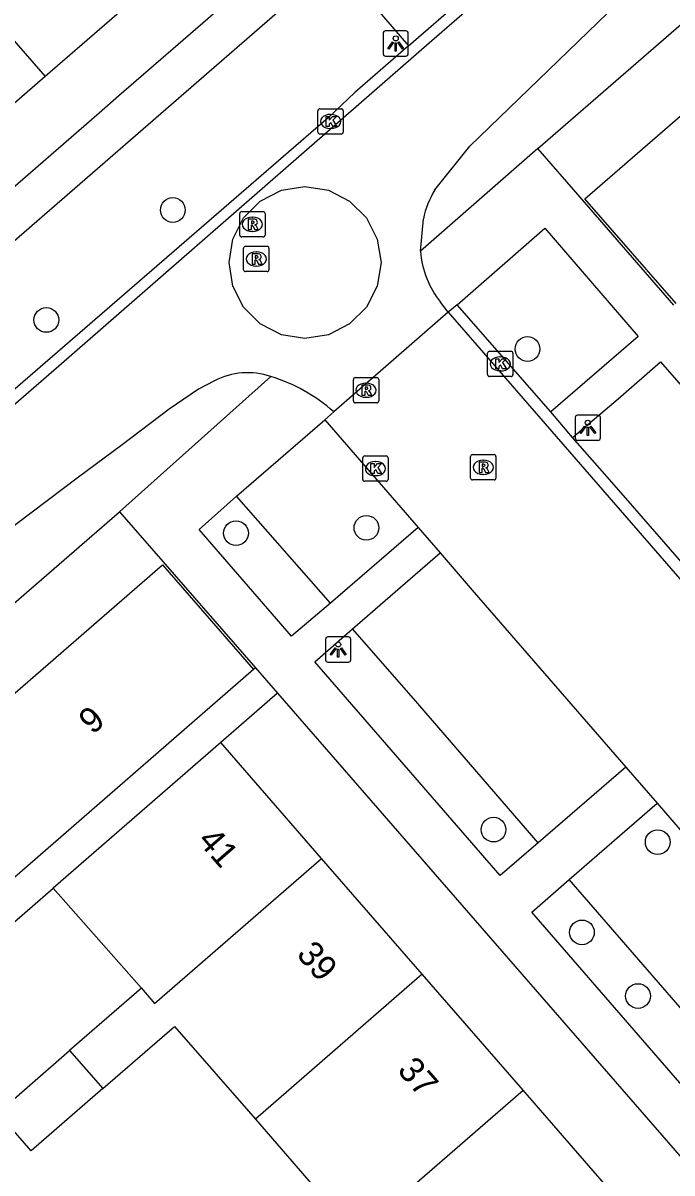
# Model space of a CAD drawing. Extents: x 155888 to 156864, y 383882 to 384671.
# Drawn here: x 156567.31 to 156592.97, y 384066.28 to 384111.77 of the extents above; entities that cross this region are included whole.
import ezdxf

# ---------------------------------------------------------------- set-up
doc = ezdxf.new("R2010")
doc.units = 0
for name, color, linetype in [('IMGEO_Boom', 7, 'Continuous'), ('IMGEO_Kolk', 7, 'Continuous'), ('IMGEO_Lichtpunt', 7, 'Continuous'), ('IMGEO_Pand', 7, 'Continuous'), ('IMGEO_Pand_nummerreeks', 7, 'Continuous'), ('IMGEO_Parkeervlak_open', 7, 'Continuous'), ('IMGEO_Rijbaan_lokaal_gesloten', 7, 'Continuous'), ('IMGEO_Rijbaan_lokaal_open', 7, 'Continuous'), ('IMGEO_Rioolput', 7, 'Continuous'), ('IMGEO_Voetpad_open', 7, 'Continuous')]:
    doc.layers.add(name, color=color, linetype=linetype)

msp = doc.modelspace()

# ---------------------------------------------------------------- linework, layer by layer
at = {"layer": 'IMGEO_Boom'}
for centre in [(156573.237, 384104.376), (156568.236, 384100.027), (156587.258, 384098.878), (156575.735, 384091.594), (156580.891, 384091.805), (156585.915, 384079.868), (156592.406, 384079.372), (156589.41, 384075.802), (156591.628, 384073.284)]:
    msp.add_circle(centre, 0.489, dxfattribs=at)
at = {"layer": 'IMGEO_Kolk'}
for p, q in [((156578.972, 384107.452), (156578.972, 384108.304)), ((156579.047, 384108.378), (156579.899, 384108.378)), ((156579.973, 384108.304), (156579.973, 384107.452)), ((156579.46, 384108.158), (156579.485, 384108.158)), ((156579.899, 384107.378), (156579.047, 384107.378)), ((156579.483, 384107.598), (156579.458, 384107.598)), ((156585.682, 384097.865), (156585.682, 384098.717)), ((156585.757, 384098.791), (156586.609, 384098.791)), ((156586.683, 384098.717), (156586.683, 384097.865)), ((156586.17, 384098.571), (156586.195, 384098.571)), ((156586.193, 384098.011), (156586.168, 384098.011)), ((156586.609, 384097.791), (156585.757, 384097.791)), ((156580.823, 384094.648), (156581.675, 384094.648)), ((156580.748, 384093.722), (156580.748, 384094.574)), ((156581.236, 384094.428), (156581.261, 384094.428)), ((156581.749, 384094.574), (156581.749, 384093.722)), ((156581.259, 384093.868), (156581.234, 384093.868)), ((156581.675, 384093.648), (156580.823, 384093.648))]:
    msp.add_line(p, q, dxfattribs=at)
for points in [[(156578.972, 384107.452), (156578.972, 384108.304)], [(156579.047, 384108.378), (156579.899, 384108.378)], [(156579.973, 384108.304), (156579.973, 384107.452)], [(156579.293, 384108.078), (156579.416, 384108.078), (156579.416, 384107.927), (156579.546, 384108.078), (156579.71, 384108.078), (156579.564, 384107.927), (156579.717, 384107.678), (156579.565, 384107.678), (156579.48, 384107.842), (156579.416, 384107.775), (156579.416, 384107.678), (156579.293, 384107.678), (156579.293, 384108.078)], [(156579.899, 384107.378), (156579.047, 384107.378)], [(156585.682, 384097.865), (156585.682, 384098.717)], [(156585.757, 384098.791), (156586.609, 384098.791)], [(156586.683, 384098.717), (156586.683, 384097.865)], [(156586.003, 384098.491), (156586.126, 384098.491), (156586.126, 384098.34), (156586.256, 384098.491), (156586.42, 384098.491), (156586.274, 384098.34), (156586.427, 384098.091), (156586.275, 384098.091), (156586.19, 384098.255), (156586.126, 384098.188), (156586.126, 384098.091), (156586.003, 384098.091), (156586.003, 384098.491)], [(156586.609, 384097.791), (156585.757, 384097.791)], [(156580.823, 384094.648), (156581.675, 384094.648)], [(156580.748, 384093.722), (156580.748, 384094.574)], [(156581.069, 384094.348), (156581.192, 384094.348), (156581.192, 384094.197), (156581.322, 384094.348), (156581.486, 384094.348), (156581.34, 384094.197), (156581.493, 384093.948), (156581.341, 384093.948), (156581.256, 384094.112), (156581.192, 384094.045), (156581.192, 384093.948), (156581.069, 384093.948), (156581.069, 384094.348)], [(156581.749, 384094.574), (156581.749, 384093.722)], [(156581.675, 384093.648), (156580.823, 384093.648)]]:
    msp.add_lwpolyline(points, dxfattribs=at)
for centre, start, end in [((156579.049, 384108.302), 91.552, 178.448), ((156579.049, 384108.302), 91.552, 178.448), ((156579.897, 384108.302), 1.552, 88.448), ((156579.897, 384108.302), 1.552, 88.448), ((156579.049, 384107.454), 181.552, 268.448), ((156579.049, 384107.454), 181.552, 268.448), ((156579.897, 384107.454), 271.552, 358.448), ((156579.897, 384107.454), 271.552, 358.448), ((156585.759, 384098.715), 91.552, 178.448), ((156585.759, 384098.715), 91.552, 178.448), ((156586.607, 384098.715), 1.552, 88.448), ((156586.607, 384098.715), 1.552, 88.448), ((156585.759, 384097.867), 181.552, 268.448), ((156585.759, 384097.867), 181.552, 268.448), ((156586.607, 384097.867), 271.552, 358.448), ((156586.607, 384097.867), 271.552, 358.448), ((156580.825, 384094.572), 91.552, 178.448), ((156580.825, 384094.572), 91.552, 178.448), ((156581.673, 384094.572), 1.552, 88.448), ((156581.673, 384094.572), 1.552, 88.448), ((156580.825, 384093.724), 181.552, 268.448), ((156580.825, 384093.724), 181.552, 268.448), ((156581.673, 384093.724), 271.552, 358.448), ((156581.673, 384093.724), 271.552, 358.448)]:
    msp.add_arc(centre, 0.0765, start, end, dxfattribs=at)
for centre, major_axis, ratio, start_param, end_param in [((156579.459, 384107.878), (-0.387, 0.002), 0.722429, 4.712389, 7.853982), ((156579.484, 384107.878), (-0.39, 0.002), 0.717154, 1.570796, 4.712389), ((156586.169, 384098.291), (-0.387, 0.002), 0.722429, 4.712389, 7.853982), ((156586.194, 384098.291), (-0.39, 0.002), 0.717154, 1.570796, 4.712389), ((156581.235, 384094.148), (-0.387, 0.002), 0.722429, 4.712389, 7.853982), ((156581.26, 384094.148), (-0.39, 0.002), 0.717154, 1.570796, 4.712389)]:
    msp.add_ellipse(centre, major_axis=major_axis, ratio=ratio, start_param=start_param, end_param=end_param, dxfattribs=at)
at = {"layer": 'IMGEO_Lichtpunt'}
for p, q in [((156582.451, 384111.462), (156581.643, 384111.462)), ((156582.451, 384111.462), (156581.643, 384111.462)), ((156581.549, 384111.367), (156581.549, 384110.56)), ((156581.549, 384111.367), (156581.549, 384110.56)), ((156582.545, 384110.56), (156582.545, 384111.367)), ((156582.545, 384110.56), (156582.545, 384111.367)), ((156581.643, 384110.466), (156582.451, 384110.466)), ((156581.643, 384110.466), (156582.451, 384110.466)), ((156589.143, 384096.167), (156589.143, 384095.36)), ((156589.143, 384096.167), (156589.143, 384095.36)), ((156590.045, 384096.262), (156589.237, 384096.262)), ((156590.045, 384096.262), (156589.237, 384096.262)), ((156590.139, 384095.36), (156590.139, 384096.167)), ((156590.139, 384095.36), (156590.139, 384096.167)), ((156589.237, 384095.266), (156590.045, 384095.266)), ((156589.237, 384095.266), (156590.045, 384095.266)), ((156579.275, 384087.394), (156579.275, 384086.587)), ((156579.275, 384087.394), (156579.275, 384086.587)), ((156580.177, 384087.489), (156579.369, 384087.489)), ((156580.177, 384087.489), (156579.369, 384087.489)), ((156580.271, 384086.587), (156580.271, 384087.394)), ((156580.271, 384086.587), (156580.271, 384087.394)), ((156579.369, 384086.493), (156580.177, 384086.493)), ((156579.369, 384086.493), (156580.177, 384086.493))]:
    msp.add_line(p, q, dxfattribs=at)
for points in [[(156581.923, 384111.031), (156581.962, 384111.003), (156581.774, 384110.741), (156581.736, 384110.768), (156581.923, 384111.031)], [(156582.135, 384111.003), (156582.173, 384111.03), (156582.36, 384110.768), (156582.321, 384110.74), (156582.135, 384111.003)], [(156582.025, 384110.983), (156582.072, 384110.983), (156582.072, 384110.661), (156582.025, 384110.661), (156582.025, 384110.983)], [(156589.517, 384095.831), (156589.556, 384095.803), (156589.368, 384095.541), (156589.33, 384095.568), (156589.517, 384095.831)], [(156589.619, 384095.783), (156589.666, 384095.783), (156589.666, 384095.461), (156589.619, 384095.461), (156589.619, 384095.783)], [(156589.729, 384095.803), (156589.767, 384095.83), (156589.954, 384095.568), (156589.915, 384095.54), (156589.729, 384095.803)], [(156579.649, 384087.058), (156579.688, 384087.03), (156579.5, 384086.768), (156579.462, 384086.795), (156579.649, 384087.058)], [(156579.751, 384087.01), (156579.798, 384087.01), (156579.798, 384086.688), (156579.751, 384086.688), (156579.751, 384087.01)], [(156579.861, 384087.03), (156579.899, 384087.057), (156580.086, 384086.795), (156580.047, 384086.767), (156579.861, 384087.03)]]:
    msp.add_lwpolyline(points, dxfattribs=at)
for centre in [(156582.048, 384111.165), (156589.642, 384095.965), (156579.774, 384087.192)]:
    msp.add_circle(centre, 0.0994, dxfattribs=at)
for centre, start, end in [((156581.643, 384111.367), 90, 180), ((156581.643, 384111.367), 90, 180), ((156582.451, 384111.367), 0, 90), ((156582.451, 384111.367), 0, 90), ((156581.643, 384110.56), 180, 270), ((156581.643, 384110.56), 180, 270), ((156582.451, 384110.56), 270, 0), ((156582.451, 384110.56), 270, 360), ((156589.237, 384096.167), 90, 180), ((156589.237, 384096.167), 90, 180), ((156590.045, 384096.167), 0, 90), ((156590.045, 384096.167), 0, 90), ((156589.237, 384095.36), 180, 270), ((156589.237, 384095.36), 180, 270), ((156590.045, 384095.36), 270, 0), ((156590.045, 384095.36), 270, 360), ((156579.369, 384087.394), 90, 180), ((156579.369, 384087.394), 90, 180), ((156580.177, 384087.394), 0, 90), ((156580.177, 384087.394), 0, 90), ((156579.369, 384086.587), 180, 270), ((156579.369, 384086.587), 180, 270), ((156580.177, 384086.587), 270, 0), ((156580.177, 384086.587), 270, 360)]:
    msp.add_arc(centre, 0.0946, start, end, dxfattribs=at)
at = {"layer": 'IMGEO_Pand'}
for points in [[(156560.961, 384117.973), (156568.188, 384109.654)], [(156572.48, 384113.384), (156568.188, 384109.654)], [(156593.133, 384100.673), (156589.53, 384104.822), (156599.132, 384113.164)], [(156568.188, 384109.654), (156563.88, 384105.911)], [(156563.279, 384082.047), (156572.833, 384090.346), (156576.432, 384086.204)], [(156576.432, 384086.204), (156566.883, 384077.899)], [(156575.131, 384083.315), (156568.505, 384077.555)], [(156579.116, 384078.729), (156575.131, 384083.315)], [(156571.995, 384073.595), (156572.516, 384072.995), (156579.116, 384078.729)], [(156583.1, 384074.145), (156579.116, 384078.729)], [(156568.505, 384077.555), (156571.995, 384073.595)], [(156583.1, 384074.145), (156576.499, 384068.41)], [(156587.084, 384069.561), (156583.1, 384074.145)], [(156571.995, 384073.595), (156569.158, 384071.13)], [(156570.469, 384069.621), (156573.306, 384072.086), (156576.499, 384068.41)], [(156570.469, 384069.621), (156567.631, 384067.156), (156566.842, 384068.065), (156566.32, 384068.665), (156569.158, 384071.13)], [(156569.158, 384071.13), (156570.469, 384069.621)], [(156579.882, 384064.517), (156580.483, 384063.825), (156587.084, 384069.561)], [(156591.067, 384064.978), (156587.084, 384069.561)], [(156576.499, 384068.41), (156579.882, 384064.517)]]:
    msp.add_lwpolyline(points, dxfattribs=at)
at = {"layer": 'IMGEO_Parkeervlak_open'}
for points in [[(156579.467, 384088.82), (156575.754, 384093.051)], [(156587.675, 384079.35), (156582.75, 384085.048), (156580.345, 384087.815)], [(156595.54, 384070.25), (156588.905, 384077.888)]]:
    msp.add_lwpolyline(points, dxfattribs=at)
at = {"layer": 'IMGEO_Rijbaan_lokaal_gesloten'}
for points in [[(156528.389, 384063.906), (156532.781, 384067.236), (156536.903, 384070.55), (156552.177, 384083.855), (156568.729, 384098.213), (156583.48, 384111.077), (156616.441, 384139.692), (156618.873, 384141.904), (156620.066, 384143.035), (156621.243, 384144.182), (156623.55, 384146.525), (156624.152, 384147.224), (156624.451, 384147.625)], [(156583.599, 384105.173), (156584.982, 384106.904), (156592.374, 384114.06), (156593.839, 384115.427), (156617.343, 384135.911), (156620.351, 384138.467), (156622.416, 384140.04), (156625.179, 384141.829)], [(156583.03, 384102.742), (156583.141, 384104.026)], [(156584.127, 384100.331), (156583.822, 384100.726)], [(156584.127, 384100.331), (156579.597, 384096.394)], [(156584.127, 384100.331), (156646.454, 384028.54), (156658.614, 384014.564)], [(156574.884, 384097.615), (156574.254, 384097.287), (156573.089, 384096.493), (156571.232, 384095.093), (156569.511, 384093.811), (156565.774, 384090.997), (156564.52, 384089.962), (156545.807, 384073.68), (156537.825, 384066.685), (156535.938, 384064.836), (156531.519, 384060.256)], [(156579.597, 384096.394), (156579.244, 384096.079)], [(156579.244, 384096.079), (156582.931, 384091.822)], [(156582.931, 384091.822), (156583.811, 384090.821)], [(156583.811, 384090.821), (156585.156, 384089.249), (156586.193, 384088.05), (156591.142, 384082.341)], [(156591.142, 384082.341), (156592.38, 384080.913)], [(156592.38, 384080.913), (156599, 384073.239)]]:
    msp.add_lwpolyline(points, dxfattribs=at)
for centre, radius, start, end in [((156586.512, 384103.345), 3.439, 147.8892, 168.5769), ((156586.652, 384103.001), 3.631, 184.0939, 218.8015), ((156576.196, 384095.132), 2.808, 70.979, 117.8538), ((156575.17, 384091.407), 6.669, 48.3992, 73.0737)]:
    msp.add_arc(centre, radius, start, end, dxfattribs=at)
at = {"layer": 'IMGEO_Rijbaan_lokaal_open'}
for points in [[(156582.557, 384110.877), (156584.84, 384112.864)], [(156582.557, 384110.877), (156580.429, 384109.026), (156579.376, 384108.016), (156553.553, 384085.656), (156552.051, 384084.344)], [(156581.319, 384101.37), (156580.893, 384100.533), (156580.228, 384099.868), (156579.391, 384099.442), (156578.462, 384099.295), (156577.534, 384099.442), (156576.696, 384099.868), (156576.032, 384100.533), (156575.605, 384101.37), (156575.458, 384102.299), (156575.605, 384103.227), (156576.032, 384104.065), (156576.696, 384104.729), (156577.534, 384105.156), (156578.462, 384105.303), (156579.391, 384105.156), (156580.228, 384104.729), (156580.893, 384104.065), (156581.319, 384103.227), (156581.467, 384102.299), (156581.319, 384101.37)], [(156584.474, 384100.632), (156584.127, 384100.331)], [(156588.18, 384096.392), (156584.474, 384100.632)], [(156589.043, 384095.382), (156588.18, 384096.392)], [(156596.453, 384086.892), (156594.77, 384088.811), (156591.404, 384092.681), (156590.413, 384093.818), (156589.043, 384095.382)]]:
    msp.add_lwpolyline(points, dxfattribs=at)
at = {"layer": 'IMGEO_Rioolput'}
for p, q in [((156575.884, 384103.385), (156575.884, 384104.237)), ((156575.959, 384104.311), (156576.811, 384104.311)), ((156576.885, 384104.237), (156576.885, 384103.385)), ((156576.372, 384104.091), (156576.397, 384104.091)), ((156576.811, 384103.311), (156575.959, 384103.311)), ((156576.395, 384103.531), (156576.37, 384103.531)), ((156576.037, 384102.014), (156576.037, 384102.866)), ((156576.112, 384102.94), (156576.964, 384102.94)), ((156577.038, 384102.866), (156577.038, 384102.014)), ((156576.525, 384102.72), (156576.55, 384102.72)), ((156576.964, 384101.94), (156576.112, 384101.94)), ((156576.548, 384102.16), (156576.523, 384102.16)), ((156580.376, 384096.823), (156580.376, 384097.675)), ((156580.451, 384097.749), (156581.303, 384097.749)), ((156580.864, 384097.529), (156580.889, 384097.529)), ((156581.377, 384097.675), (156581.377, 384096.823)), ((156580.887, 384096.969), (156580.862, 384096.969)), ((156581.303, 384096.749), (156580.451, 384096.749)), ((156585.009, 384093.773), (156585.009, 384094.625)), ((156585.084, 384094.699), (156585.936, 384094.699)), ((156586.01, 384094.625), (156586.01, 384093.773)), ((156585.497, 384094.479), (156585.522, 384094.479)), ((156585.52, 384093.919), (156585.495, 384093.919)), ((156585.936, 384093.699), (156585.084, 384093.699))]:
    msp.add_line(p, q, dxfattribs=at)
for points in [[(156575.884, 384103.385), (156575.884, 384104.237)], [(156575.959, 384104.311), (156576.811, 384104.311)], [(156576.885, 384104.237), (156576.885, 384103.385)], [(156576.473, 384104.009), (156576.221, 384104.011), (156576.221, 384103.611)], [(156576.221, 384103.611), (156576.345, 384103.611), (156576.345, 384103.773), (156576.356, 384103.773)], [(156576.399, 384103.93), (156576.345, 384103.93), (156576.345, 384103.849)], [(156576.345, 384103.849), (156576.397, 384103.849)], [(156576.403, 384103.744), (156576.474, 384103.611), (156576.614, 384103.611), (156576.549, 384103.737)], [(156576.811, 384103.311), (156575.959, 384103.311)], [(156576.037, 384102.014), (156576.037, 384102.866)], [(156576.112, 384102.94), (156576.964, 384102.94)], [(156577.038, 384102.866), (156577.038, 384102.014)], [(156576.626, 384102.638), (156576.374, 384102.64), (156576.374, 384102.24)], [(156576.374, 384102.24), (156576.498, 384102.24), (156576.498, 384102.402), (156576.509, 384102.402)], [(156576.552, 384102.559), (156576.498, 384102.559), (156576.498, 384102.478)], [(156576.498, 384102.478), (156576.55, 384102.478)], [(156576.556, 384102.373), (156576.627, 384102.24), (156576.767, 384102.24), (156576.702, 384102.366)], [(156576.964, 384101.94), (156576.112, 384101.94)], [(156580.376, 384096.823), (156580.376, 384097.675)], [(156580.451, 384097.749), (156581.303, 384097.749)], [(156580.965, 384097.447), (156580.713, 384097.449), (156580.713, 384097.049)], [(156580.891, 384097.368), (156580.837, 384097.368), (156580.837, 384097.287)], [(156581.377, 384097.675), (156581.377, 384096.823)], [(156580.713, 384097.049), (156580.837, 384097.049), (156580.837, 384097.211), (156580.848, 384097.211)], [(156580.837, 384097.287), (156580.889, 384097.287)], [(156580.895, 384097.182), (156580.966, 384097.049), (156581.106, 384097.049), (156581.041, 384097.175)], [(156581.303, 384096.749), (156580.451, 384096.749)], [(156585.009, 384093.773), (156585.009, 384094.625)], [(156585.084, 384094.699), (156585.936, 384094.699)], [(156586.01, 384094.625), (156586.01, 384093.773)], [(156585.598, 384094.397), (156585.346, 384094.399), (156585.346, 384093.999)], [(156585.346, 384093.999), (156585.47, 384093.999), (156585.47, 384094.161), (156585.481, 384094.161)], [(156585.524, 384094.318), (156585.47, 384094.318), (156585.47, 384094.237)], [(156585.47, 384094.237), (156585.522, 384094.237)], [(156585.528, 384094.132), (156585.599, 384093.999), (156585.739, 384093.999), (156585.674, 384094.125)], [(156585.936, 384093.699), (156585.084, 384093.699)]]:
    msp.add_lwpolyline(points, dxfattribs=at)
for centre, radius, start, end in [((156575.961, 384104.235), 0.0765, 91.552, 178.448), ((156575.961, 384104.235), 0.0765, 91.552, 178.448), ((156576.809, 384104.235), 0.0765, 1.552, 88.448), ((156576.809, 384104.235), 0.0765, 1.552, 88.448), ((156576.355, 384103.72), 0.0533, 26.0293, 88.6989), ((156576.381, 384104.038), 0.19, 274.7715, 282.9687), ((156576.405, 384103.834), 0.0964, 77.0061, 93.1865), ((156576.419, 384103.891), 0.0378, 276.6634, 79.6772), ((156576.472, 384103.899), 0.109, 350.3612, 89.416), ((156576.47, 384103.899), 0.112, 277.5842, 350.9817), ((156576.454, 384103.684), 0.108, 29.5134, 73.7905), ((156575.961, 384103.387), 0.0765, 181.552, 268.448), ((156575.961, 384103.387), 0.0765, 181.552, 268.448), ((156576.809, 384103.387), 0.0765, 271.552, 358.448), ((156576.809, 384103.387), 0.0765, 271.552, 358.448), ((156576.114, 384102.864), 0.0765, 91.552, 178.448), ((156576.114, 384102.864), 0.0765, 91.552, 178.448), ((156576.962, 384102.864), 0.0765, 1.552, 88.448), ((156576.962, 384102.864), 0.0765, 1.552, 88.448), ((156576.508, 384102.349), 0.0533, 26.0293, 88.6989), ((156576.534, 384102.667), 0.19, 274.7715, 282.9687), ((156576.558, 384102.463), 0.0964, 77.0061, 93.1865), ((156576.572, 384102.52), 0.0378, 276.6634, 79.6772), ((156576.625, 384102.528), 0.109, 350.3612, 89.416), ((156576.623, 384102.528), 0.112, 277.5842, 350.9817), ((156576.607, 384102.313), 0.108, 29.5134, 73.7905), ((156576.114, 384102.016), 0.0765, 181.552, 268.448), ((156576.114, 384102.016), 0.0765, 181.552, 268.448), ((156576.962, 384102.016), 0.0765, 271.552, 358.448), ((156576.962, 384102.016), 0.0765, 271.552, 358.448), ((156580.453, 384097.673), 0.0765, 91.552, 178.448), ((156580.453, 384097.673), 0.0765, 91.552, 178.448), ((156580.897, 384097.272), 0.0964, 77.0061, 93.1865), ((156580.911, 384097.329), 0.0378, 276.6634, 79.6772), ((156580.964, 384097.337), 0.109, 350.3612, 89.416), ((156581.301, 384097.673), 0.0765, 1.552, 88.448), ((156581.301, 384097.673), 0.0765, 1.552, 88.448), ((156580.847, 384097.158), 0.0533, 26.0293, 88.6989), ((156580.873, 384097.476), 0.19, 274.7715, 282.9687), ((156580.962, 384097.337), 0.112, 277.5842, 350.9817), ((156580.946, 384097.122), 0.108, 29.5134, 73.7905), ((156580.453, 384096.825), 0.0765, 181.552, 268.448), ((156580.453, 384096.825), 0.0765, 181.552, 268.448), ((156581.301, 384096.825), 0.0765, 271.552, 358.448), ((156581.301, 384096.825), 0.0765, 271.552, 358.448), ((156585.086, 384094.623), 0.0765, 91.552, 178.448), ((156585.086, 384094.623), 0.0765, 91.552, 178.448), ((156585.934, 384094.623), 0.0765, 1.552, 88.448), ((156585.934, 384094.623), 0.0765, 1.552, 88.448), ((156585.48, 384094.108), 0.0533, 26.0293, 88.6989), ((156585.506, 384094.426), 0.19, 274.7715, 282.9687), ((156585.53, 384094.222), 0.0964, 77.0061, 93.1865), ((156585.544, 384094.279), 0.0378, 276.6634, 79.6772), ((156585.597, 384094.287), 0.109, 350.3612, 89.416), ((156585.595, 384094.287), 0.112, 277.5842, 350.9817), ((156585.579, 384094.072), 0.108, 29.5134, 73.7905), ((156585.086, 384093.775), 0.0765, 181.552, 268.448), ((156585.086, 384093.775), 0.0765, 181.552, 268.448), ((156585.934, 384093.775), 0.0765, 271.552, 358.448), ((156585.934, 384093.775), 0.0765, 271.552, 358.448)]:
    msp.add_arc(centre, radius, start, end, dxfattribs=at)
for centre, major_axis, ratio, start_param, end_param in [((156576.371, 384103.811), (-0.387, 0.002), 0.722429, 4.712389, 7.853982), ((156576.396, 384103.811), (-0.39, 0.002), 0.717154, 1.570796, 4.712389), ((156576.524, 384102.44), (-0.387, 0.002), 0.722429, 4.712389, 7.853982), ((156576.549, 384102.44), (-0.39, 0.002), 0.717154, 1.570796, 4.712389), ((156580.863, 384097.249), (-0.387, 0.002), 0.722429, 4.712389, 7.853982), ((156580.888, 384097.249), (-0.39, 0.002), 0.717154, 1.570796, 4.712389), ((156585.496, 384094.199), (-0.387, 0.002), 0.722429, 4.712389, 7.853982), ((156585.521, 384094.199), (-0.39, 0.002), 0.717154, 1.570796, 4.712389)]:
    msp.add_ellipse(centre, major_axis=major_axis, ratio=ratio, start_param=start_param, end_param=end_param, dxfattribs=at)
at = {"layer": 'IMGEO_Voetpad_open'}
for points in [[(156587.667, 384106.816), (156626.242, 384140.297)], [(156576.865, 384117.193), (156578.489, 384115.359), (156574.615, 384111.942), (156571.103, 384108.893), (156570.32, 384108.213), (156566.807, 384105.148), (156566.005, 384104.472), (156562.509, 384101.408), (156561.721, 384100.736), (156558.21, 384097.677), (156557.417, 384096.994), (156553.895, 384093.933), (156553.113, 384093.241), (156549.6, 384090.192), (156548.818, 384089.519), (156548.425, 384089.16), (156548.108, 384088.885), (156546.461, 384090.777)], [(156552.051, 384084.344), (156550.734, 384085.846), (156549.131, 384087.675), (156579.669, 384114.204), (156581.24, 384112.394), (156582.557, 384110.877)], [(156587.667, 384106.816), (156583.03, 384102.742)], [(156593.045, 384100.611), (156589.344, 384104.881), (156587.667, 384106.816)], [(156584.474, 384100.632), (156587.944, 384103.66), (156591.629, 384099.371), (156588.18, 384096.392)], [(156589.043, 384095.382), (156590.839, 384096.907), (156592.517, 384098.365), (156594.87, 384095.667), (156598.216, 384091.811), (156599.93, 384089.87), (156596.453, 384086.892)], [(156571.128, 384092.444), (156577.111, 384097.787)], [(156575.754, 384093.051), (156579.244, 384096.079)], [(156579.467, 384088.82), (156577.934, 384087.519), (156574.284, 384091.742), (156575.754, 384093.051)], [(156532.534, 384058.953), (156571.128, 384092.444)], [(156571.128, 384092.444), (156572.838, 384090.477), (156576.501, 384086.263)], [(156582.931, 384091.822), (156579.467, 384088.82)], [(156580.345, 384087.815), (156582.022, 384089.27), (156583.811, 384090.821)], [(156587.675, 384079.35), (156586.172, 384078.05), (156578.847, 384086.504), (156580.345, 384087.815)], [(156576.501, 384086.263), (156576.432, 384086.204)], [(156576.501, 384086.263), (156577.371, 384085.262)], [(156577.371, 384085.262), (156575.131, 384083.315)], [(156577.371, 384085.262), (156609.255, 384048.581)], [(156591.142, 384082.341), (156587.675, 384079.35)], [(156588.905, 384077.888), (156592.38, 384080.913)], [(156595.54, 384070.25), (156594.055, 384068.957), (156587.433, 384076.599), (156588.905, 384077.888)], [(156592.123, 384033.709), (156560.241, 384070.368), (156568.505, 384077.555)]]:
    msp.add_lwpolyline(points, dxfattribs=at)

# ---------------------------------------------------------------- texts
at = {"layer": 'IMGEO_Pand_nummerreeks'}
for s, rotation, p in [('9', 40.9798, (156570.065, 384083.597)), ('41', 310.9949, (156574.18, 384079.41)), ('39', 310.9949, (156578.09, 384074.911)), ('37', 310.9949, (156582.075, 384070.326))]:
    msp.add_text(s, height=1, rotation=rotation, dxfattribs=at).set_placement(p)

doc.saveas('drawing.dxf')
